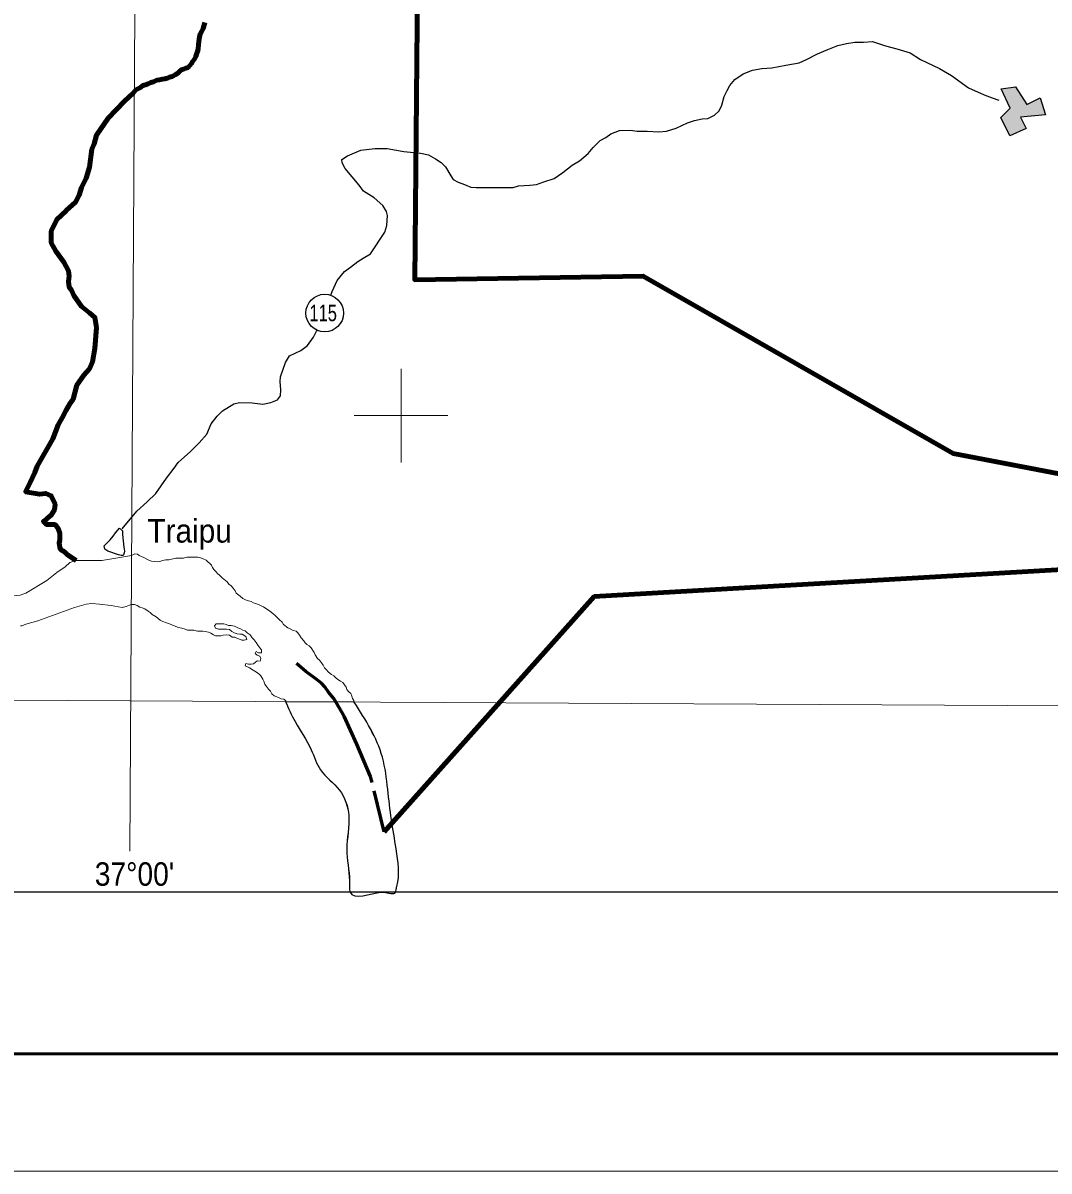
# Model space of a CAD drawing. Extents: x 553962 to 842807, y 8883888 to 9032388.
# Drawn here: x 716936 to 738822, y 8883888 to 8908376 of the extents above; entities that cross this region are included whole.
import ezdxf
from ezdxf.enums import TextEntityAlignment as Align

# ---------------------------------------------------------------- set-up
doc = ezdxf.new("R2010")
doc.units = 0
doc.header["$LTSCALE"] = 150
doc.linetypes.add('LONG_DASH_SHORT_DASH', pattern=[9.9, 6, -1.2, 1.5, -1.2])
for name, color, linetype, lineweight in [('1', 7, 'Continuous', 13), ('12', 7, 'Continuous', 25), ('2', 7, 'Continuous', 13), ('21', 7, 'Continuous', 25), ('24', 7, 'Continuous', 25), ('25', 7, 'Continuous', 13), ('3', 7, 'Continuous', 13), ('48', 7, 'Continuous', 25), ('53', 7, 'Continuous', 106), ('7', 7, 'LONG_DASH_SHORT_DASH', 60), ('9', 7, 'Continuous', 90)]:
    doc.layers.add(name, color=color, linetype=linetype, lineweight=lineweight)
doc.layers.add('41', color=7, linetype='Continuous')
doc.layers.add('46', color=7, linetype='Continuous')

msp = doc.modelspace()

# ---------------------------------------------------------------- hatches: boundary and pattern name
at = {"layer": '21'}
msp.add_hatch(color=256, dxfattribs=at).paths.add_polyline_path([(737801.5, 8906970.9), (738106.6, 8907012.5), (738347.6, 8906633.5), (738630.7, 8906778.2), (738745.6, 8906416), (738212.5, 8906368.9), (738331.1, 8906121.9), (737984.3, 8905966.4), (737794.3, 8906356.6), (737990.6, 8906555.2)])

# ---------------------------------------------------------------- linework, layer by layer
at = {"layer": '1'}
for points in [[(719978.9, 9023574.5), (719561.6, 8949232.2), (719215.6, 8890710.6)], [(564751.7, 8894587.5), (664411.9, 8894209.9), (791388.5, 8893536.2)]]:
    msp.add_lwpolyline(points, dxfattribs=at)
at = {"layer": '12'}
for points in [[(732698.6, 8907406), (732912.6, 8907415.8), (733208.3, 8907476.3), (733493.7, 8907526.8), (733646.8, 8907597.8), (733881.6, 8907714.5), (734106.1, 8907810.9), (734320.4, 8907892), (734498.8, 8907937.5), (734677.2, 8907962.7), (734865.7, 8907967.4), (735054.3, 8907977.3), (735334.1, 8907885.1), (735578.4, 8907823.5), (735863.4, 8907741.4), (736076.8, 8907598.4), (736483.7, 8907404.1), (736742.9, 8907255.9), (737103.6, 8906990.3), (737439.3, 8906842), (737612.3, 8906775.4), (737750.2, 8906727.3)], [(727039.6, 8904864.2), (727284.1, 8904868.9), (727391.1, 8904868.7), (727508.4, 8904899), (727747.9, 8904919), (727890.6, 8904928.9), (728048.7, 8904984.6), (728268, 8905055.5), (728451.9, 8905187.7), (728651.2, 8905340.1), (728809.4, 8905436.6), (728993.4, 8905594.2), (729095.8, 8905716.2), (729249.1, 8905868.8), (729371.7, 8905934.8), (729473.8, 8906011), (729657.5, 8906082), (729896.9, 8906091.7), (730039.5, 8906071.1), (730253.5, 8906065.6), (730497.9, 8906055), (730661, 8906064.9), (730870.1, 8906130.7), (731110, 8906247.4), (731263, 8906293), (731426.1, 8906328.3), (731543.3, 8906338.3), (731686.2, 8906409.4), (731788.5, 8906500.9), (731839.8, 8906623.1), (731891.5, 8906806.3), (731958.2, 8906938.7), (732014.6, 8907040.4), (732122.1, 8907172.7), (732300.8, 8907289.5), (732499.7, 8907365.6), (732698.6, 8907406)], [(723502.8, 8902567), (723531.6, 8902649.7), (723639.5, 8902883.8), (723793, 8903072), (723920.7, 8903168.5), (724079.1, 8903290.5), (724191.4, 8903356.5), (724349.7, 8903453), (724652, 8903916), (724698.3, 8904058.6), (724714.4, 8904272.5), (724689.2, 8904354.1), (724613.3, 8904481.5), (724430.5, 8904644.9), (724201.8, 8904787.9), (724110.5, 8904915.5), (723811.3, 8905272.6), (723745.5, 8905389.9), (723740.7, 8905461.2), (723858.1, 8905542.5), (724143.8, 8905659.1), (724444.6, 8905699.3), (724704.4, 8905698.9), (725060.7, 8905637.1), (725417.2, 8905595.7), (725585.2, 8905564.8), (725732.6, 8905477.9), (725859.7, 8905396.2), (725945.9, 8905304.3), (726062.4, 8905115.6), (726113.1, 8905039.1), (726219.8, 8904977.8), (726352.1, 8904931.7), (726489.4, 8904870.3), (726601.5, 8904865), (727039.6, 8904864.2)], [(719051.7, 8897586.9), (719362.5, 8897965.7), (719587.4, 8898163.9), (719771.5, 8898341.9), (719996.8, 8898667.5), (720160.6, 8898881.1), (720247.7, 8899003.2), (720508.3, 8899237.1), (720697.5, 8899420.1), (720856.1, 8899608.3), (720953.7, 8899827.2), (721076.6, 8899989.9), (721194.2, 8900101.8), (721434.2, 8900254.2), (721551.4, 8900279.4), (721826.5, 8900273.8), (722050.5, 8900248), (722223.9, 8900278.2), (722366.7, 8900339.1), (722428.2, 8900425.6), (722433.7, 8900552.9), (722424.2, 8900726.1), (722429.7, 8900828), (722532.7, 8901133.4), (722624.9, 8901275.9), (722864.7, 8901387.5), (723007.8, 8901494.2), (723130.7, 8901677.4), (723197.4, 8901799.6), (723209.3, 8901823.1)]]:
    msp.add_lwpolyline(points, dxfattribs=at)
at = {"layer": '2'}
for p, q in [((725000, 8899000), (725000, 8901000)), ((724000, 8900000), (726000, 8900000))]:
    msp.add_line(p, q, dxfattribs=at)
at = {"layer": '21'}
for points in [[(737801.5, 8906970.9), (738106.6, 8907012.5), (738347.6, 8906633.5), (738630.7, 8906778.2), (738745.6, 8906416), (738212.5, 8906368.9), (738331.1, 8906121.9), (737984.3, 8905966.4), (737794.3, 8906356.6), (737990.6, 8906555.2)], [(718993.1, 8897599.9), (719057.4, 8897544.6), (719055.9, 8897461.4), (719085.3, 8897192.5), (719103.1, 8897108.8), (719098.1, 8897076.1), (719079.4, 8897033), (719065.5, 8897020), (719028.2, 8897020.1), (718974.7, 8897034.1), (718746.2, 8897111.7), (718679.7, 8897153.1), (718671.6, 8897221.2), (718685, 8897240.1), (718799.2, 8897348.2), (718862.4, 8897430.9), (718906.6, 8897502.9)]]:
    msp.add_lwpolyline(points, close=True, dxfattribs=at)
at = {"layer": '24', "lineweight": 53}
for points in [[(720818, 8908383.6), (720797.2, 8908307.3), (720781.6, 8908256.4), (720750.7, 8908200.6), (720714.6, 8908139.7), (720699, 8908078.7), (720693.5, 8908027.8), (720680.1, 8907917.9)], [(720680.1, 8907917.9), (720671.8, 8907819.1), (720661.2, 8907768.2), (720640.5, 8907712.3), (720624.9, 8907661.5), (720594, 8907605.6), (720558.1, 8907560), (720532.3, 8907509.3), (720496.4, 8907468.7), (720460.5, 8907428.2), (720409.6, 8907413.3), (720363.7, 8907393.2), (720312.7, 8907373.1), (720276.8, 8907337.7), (720241, 8907302.3), (720179.7, 8907267), (720118.4, 8907231.8), (720062.3, 8907216.8), (720016.4, 8907196.8), (719965.5, 8907181.8), (719909.5, 8907177.1), (719843.3, 8907162.2), (719792.3, 8907152.3), (719720.9, 8907122.2), (719664.9, 8907107.3), (719603.6, 8907077.1), (719552.6, 8907057.1), (719496.6, 8907042.2), (719445.4, 8907001.8), (719343.4, 8906951.5), (719283.6, 8906877)], [(719283.6, 8906877), (719100.8, 8906711), (718751.9, 8906345.6), (718502.7, 8905980.3), (718452.8, 8905797.7), (718403, 8905681.4), (718353.1, 8905299.5), (718286.7, 8905067), (718187, 8904867.8), (718137.2, 8904701.7), (718054.1, 8904552.2), (717859.9, 8904374.3), (717854.7, 8904369.6)], [(717854.7, 8904369.6), (717655.3, 8904186.9), (717539, 8903937.8), (717539, 8903688.8), (717638.7, 8903506.1), (717804.9, 8903273.6), (717904.6, 8903091), (717921.2, 8902974.7), (717904.6, 8902858.5), (717921.2, 8902742.3), (717971.1, 8902675.9), (718020.9, 8902559.6), (718187, 8902327.1), (718353.2, 8902194.3), (718469.5, 8902094.7), (718502.7, 8901878.8), (718469.5, 8901430.4), (718419.6, 8901148.2), (718353.2, 8900998.7), (718236.8, 8900865.9), (718087.3, 8900650), (718004.2, 8900351.1), (717937.8, 8900251.5), (717854.7, 8900118.6), (717771.7, 8899952.6), (717688.6, 8899803.1), (717572.3, 8899504.2), (717240, 8898923), (717190.1, 8898790.2), (717090.4, 8898574.3), (716990.8, 8898375.1), (717206.8, 8898341.9), (717289.8, 8898325.2), (717422.7, 8898341.9), (717539, 8898292), (717622.1, 8898109.4), (717605.5, 8897993.1), (717539, 8897876.9), (717472.6, 8897827.1), (717422.7, 8897777.3), (717372.9, 8897744.1), (717439.4, 8897677.6), (717622.1, 8897677.6), (717688.6, 8897594.6), (717721.8, 8897495), (717721.8, 8897395.3), (717721.8, 8897345.5), (717705.2, 8897279.1), (717721.8, 8897196.1), (717738.4, 8897146.3), (717821.5, 8897096.4), (717888, 8897030), (718070.7, 8896913.8)]]:
    msp.add_lwpolyline(points, dxfattribs=at)
at = {"layer": '25', "lineweight": 25}
msp.add_line((724002.8, 8893886.5), (722537.3, 8893896.5), dxfattribs=at)
msp.add_line((724002.8, 8893886.5), (722537.3, 8893896.5), dxfattribs=at)
at = {"layer": '25'}
for points in [[(716671.9, 8896141.4), (716736, 8896160), (716876.8, 8896172.9), (716996.8, 8896216.3), (717443.2, 8896481.3), (717658.9, 8896651.8), (717833.2, 8896772.8), (717934, 8896865.6), (718070.7, 8896913.8), (718220.3, 8896913.8), (718619, 8896913.8), (718918.1, 8896963.6), (719252.2, 8897020.3)], [(719252.2, 8897020.3), (719320.1, 8897049.2), (719376, 8897048.8), (719416.5, 8897018), (719467.2, 8896997.3), (719517.9, 8896971.5), (719578.7, 8896940.5), (719624.3, 8896914.8), (719680.1, 8896894), (719736.1, 8896888.6), (719797.1, 8896883.1), (719858.1, 8896887.8), (719909.1, 8896907.8), (719980.4, 8896922.7), (720046.6, 8896927.3), (720199.4, 8896962), (720255.3, 8896961.7), (720306.2, 8896961.3), (720362.2, 8896961), (720428.4, 8896980.9), (720479.3, 8896980.6), (720540.3, 8896980.2), (720606.4, 8896979.8), (720667.5, 8896979.4), (720723.3, 8896968.8), (720779.1, 8896948.1), (720845, 8896917.1), (720880.4, 8896881.2), (720920.8, 8896845.3), (720956.2, 8896809.4)], [(720956.2, 8896809.4), (720981.3, 8896763.4), (721006.4, 8896717.4), (721046.8, 8896676.4), (721082.2, 8896635.4), (721127.7, 8896594.4), (721188.3, 8896538), (721289.5, 8896455.8), (721329.8, 8896404.6), (721375.3, 8896368.7), (721420.8, 8896322.5), (721461, 8896261.2), (721486.2, 8896215.2), (721567.1, 8896148.4), (721627.8, 8896097.1), (721683.5, 8896071.3), (721749.5, 8896050.5), (721805.3, 8896034.8), (721856, 8896009), (721916.9, 8895988.3), (721972.7, 8895967.5), (722018.4, 8895946.9), (722069, 8895921.1), (722119.7, 8895885.1), (722175.4, 8895854.2), (722231, 8895808), (722271.5, 8895772), (722312, 8895741.2), (722367.5, 8895689.9), (722402.9, 8895654), (722463.5, 8895597.6), (722493.7, 8895546.5), (722584.8, 8895474.6), (722635.5, 8895453.9), (722701.4, 8895417.8), (722762.3, 8895402.1), (722802.7, 8895366.2), (722832.9, 8895320.2), (722873.2, 8895263.9), (722923.6, 8895197.3), (722953.8, 8895151.3), (722994.3, 8895120.5), (723039.9, 8895089.6), (723085.4, 8895048.6), (723145.7, 8894951.4), (723165.7, 8894895.3), (723221.1, 8894818.5), (723261.6, 8894782.6), (723301.9, 8894726.3), (723337.1, 8894675.1), (723367.3, 8894624), (723402.6, 8894583), (723453.1, 8894526.7), (723518.8, 8894475.3), (723564.4, 8894449.5), (723609.9, 8894408.5), (723655.5, 8894372.5), (723706.1, 8894336.6), (723761.8, 8894305.6), (723797.1, 8894259.6), (723827.3, 8894208.4), (723842.2, 8894157.4), (723887.6, 8894111.3), (723928.1, 8894075.3), (723948, 8894019.2)], [(719242.1, 8895974.6), (719137.8, 8895926.7), (719051.9, 8895910.8), (718819, 8895950.7), (718570.6, 8895982.3), (718406.7, 8895992.1), (718284.1, 8895976.8), (718038.4, 8895905.8), (717250.7, 8895623.3), (716998.4, 8895554.6), (716915, 8895518.1), (716881.8, 8895513.8)], [(721516.7, 8895476.3), (721445.7, 8895507.4), (721379.7, 8895523.1), (721323.7, 8895523.4), (721273, 8895544.1), (721222.2, 8895559.7), (721151.1, 8895560.2), (721054.4, 8895560.8), (721023.6, 8895520.3), (721043.6, 8895469.2), (721104.5, 8895443.3), (721160.4, 8895443), (721211.3, 8895442.7), (721277.4, 8895442.2), (721343.5, 8895436.7), (721394.1, 8895395.6), (721444.7, 8895364.7), (721505.6, 8895344), (721561.5, 8895338.5), (721612.4, 8895338.2), (721688.3, 8895286.8), (721708.2, 8895225.5), (721657.3, 8895210.6), (721606.4, 8895210.9), (721555.7, 8895231.6), (721499.9, 8895252.3), (721454.2, 8895273), (721398.3, 8895278.4), (721342.7, 8895319.6), (721276.6, 8895325.1), (721205.3, 8895320.4), (721154.4, 8895305.5), (721098.4, 8895300.7), (721042.5, 8895301.1), (720996.9, 8895326.9), (720941.1, 8895357.8), (720890.4, 8895378.5), (720824.4, 8895399.3), (720773.6, 8895399.6), (720722.7, 8895399.9), (720656.6, 8895405.4), (720580.4, 8895421.2), (720509.3, 8895426.8), (720448.2, 8895427.2), (720397.5, 8895447.9), (720326.5, 8895468.7), (720250.3, 8895484.5), (720158.9, 8895515.6), (720113.3, 8895541.4), (720062.6, 8895557), (719996.6, 8895577.8), (719920.5, 8895608.8), (719864.8, 8895634.7), (719819.3, 8895675.7), (719778.8, 8895711.6), (719692.7, 8895758), (719647.2, 8895799.1), (719606.7, 8895829.9), (719535.8, 8895876.2), (719480.1, 8895902), (719429.3, 8895917.6), (719373.6, 8895948.5), (719317.8, 8895969.3), (719266.9, 8895969.6), (719242.1, 8895974.6)], [(722073.4, 8894336.8), (722053.4, 8894382.8), (722013.2, 8894449.3), (721972.7, 8894485.2), (721917.1, 8894531.4), (721846.2, 8894572.6), (721770.2, 8894618.9), (721724.6, 8894639.6), (721673.9, 8894665.4), (721689.5, 8894716.2), (721745.3, 8894700.6), (721801.3, 8894700.2), (721852.2, 8894705), (721893.1, 8894740.4), (721934, 8894770.7), (721995, 8894765.2), (722010.6, 8894821.2), (721985.5, 8894867.2), (721934.8, 8894893), (721889.3, 8894923.8), (721909.9, 8894969.5), (721960.6, 8894943.7), (722021.6, 8894943.3), (722027.1, 8895004.4), (721986.8, 8895050.5), (721946.5, 8895106.8), (721911.2, 8895163.1), (721871, 8895219.4), (721825.5, 8895260.4), (721780.1, 8895321.8), (721719.4, 8895368.1), (721679, 8895409.1), (721628.2, 8895424.7), (721577.6, 8895455.6), (721516.7, 8895476.3)], [(722537.3, 8893896.5), (722543.5, 8893916.1), (722503.1, 8893952.1), (722447.2, 8893962.6), (722401.6, 8893983.3), (722350.9, 8894004), (722295.1, 8894024.7), (722244.5, 8894065.8), (722214.3, 8894122), (722174, 8894168.1), (722128.6, 8894224.4), (722098.4, 8894270.5), (722073.4, 8894336.8)], [(723948, 8894019.2), (723962.9, 8893968.2), (723993.2, 8893927.2), (724002.8, 8893886.5), (722537.3, 8893896.5)]]:
    msp.add_lwpolyline(points, dxfattribs=at)
at = {"layer": '25', "lineweight": 25}
for points in [[(722537.3, 8893896.5), (722740.6, 8893475.5), (723084.4, 8892873.8), (723285, 8892444), (723686.1, 8892014.3), (723886.7, 8891469.9), (723843.7, 8890753.6), (723901, 8890080.3), (723900.8, 8889934.8), (723915.3, 8889836.7), (724574.3, 8889836.7), (724631.6, 8889836.7), (724883.2, 8889836.5), (724893.2, 8889883.7), (724911.8, 8889958.1), (724898, 8890758.3), (724794.3, 8891380.3), (724717.6, 8892028.6), (724603, 8892716.2), (724002.8, 8893886.5)], [(722537.3, 8893896.5), (722740.6, 8893475.5), (723084.4, 8892873.8), (723285, 8892444), (723686.1, 8892014.3), (723886.7, 8891469.9), (723843.7, 8890753.6), (723901, 8890080.3), (723901.3, 8889998.4)], [(724811.6, 8891262.3), (724794.3, 8891380.3), (724717.6, 8892028.6), (724603, 8892716.2), (724002.8, 8893886.5)]]:
    msp.add_spline(points, degree=3, dxfattribs=at)
at = {"layer": '3'}
msp.add_lwpolyline([(842807.3, 9032387.8), (842807.3, 8883887.8), (553961.7, 8883887.8), (553961.7, 9032387.8)], close=True, dxfattribs=at)
at = {"layer": '3', "lineweight": 53}
msp.add_lwpolyline([(840307.3, 9029887.8), (840307.3, 8886387.8), (560211.7, 8886387.8), (560211.7, 9029887.8)], close=True, dxfattribs=at)
at = {"layer": '3', "lineweight": 25}
msp.add_lwpolyline([(563033.9, 9026438.8), (793061.1, 9026438.8), (793495.6, 8889836.8), (563468.3, 8889836.8)], close=True, dxfattribs=at)
at = {"layer": '48'}
msp.add_circle((723371.8, 8902188.1), 401.3, dxfattribs=at)
at = {"layer": '53'}
for points in [[(720818, 8908383.6), (720797.2, 8908307.3), (720781.6, 8908256.4), (720750.7, 8908200.6), (720714.6, 8908139.7), (720699, 8908078.7), (720693.5, 8908027.8), (720680.1, 8907917.9)], [(720818, 8908383.6), (720797.2, 8908307.3), (720781.6, 8908256.4), (720750.7, 8908200.6), (720714.6, 8908139.7), (720699, 8908078.7), (720693.5, 8908027.8), (720680.1, 8907917.9)], [(720818, 8908383.6), (720797.2, 8908307.3), (720781.6, 8908256.4), (720750.7, 8908200.6), (720714.6, 8908139.7), (720699, 8908078.7), (720693.5, 8908027.8), (720680.1, 8907917.9)], [(720680.1, 8907917.9), (720671.8, 8907819.1), (720661.2, 8907768.2), (720640.5, 8907712.3), (720624.9, 8907661.5), (720594, 8907605.6), (720558.1, 8907560), (720532.3, 8907509.3), (720496.4, 8907468.7), (720460.5, 8907428.2), (720409.6, 8907413.3), (720363.7, 8907393.2), (720312.7, 8907373.1), (720276.8, 8907337.7), (720241, 8907302.3), (720179.7, 8907267), (720118.4, 8907231.8), (720062.3, 8907216.8), (720016.4, 8907196.8), (719965.5, 8907181.8), (719909.5, 8907177.1), (719843.3, 8907162.2), (719792.3, 8907152.3), (719720.9, 8907122.2), (719664.9, 8907107.3), (719603.6, 8907077.1), (719552.6, 8907057.1), (719496.6, 8907042.2), (719445.4, 8907001.8), (719343.4, 8906951.5), (719283.6, 8906877)], [(720680.1, 8907917.9), (720671.8, 8907819.1), (720661.2, 8907768.2), (720640.5, 8907712.3), (720624.9, 8907661.5), (720594, 8907605.6), (720558.1, 8907560), (720532.3, 8907509.3), (720496.4, 8907468.7), (720460.5, 8907428.2), (720409.6, 8907413.3), (720363.7, 8907393.2), (720312.7, 8907373.1), (720276.8, 8907337.7), (720241, 8907302.3), (720179.7, 8907267), (720118.4, 8907231.8), (720062.3, 8907216.8), (720016.4, 8907196.8), (719965.5, 8907181.8), (719909.5, 8907177.1), (719843.3, 8907162.2), (719792.3, 8907152.3), (719720.9, 8907122.2), (719664.9, 8907107.3), (719603.6, 8907077.1), (719552.6, 8907057.1), (719496.6, 8907042.2), (719445.4, 8907001.8), (719343.4, 8906951.5), (719283.6, 8906877)], [(720680.1, 8907917.9), (720671.8, 8907819.1), (720661.2, 8907768.2), (720640.5, 8907712.3), (720624.9, 8907661.5), (720594, 8907605.6), (720558.1, 8907560), (720532.3, 8907509.3), (720496.4, 8907468.7), (720460.5, 8907428.2), (720409.6, 8907413.3), (720363.7, 8907393.2), (720312.7, 8907373.1), (720276.8, 8907337.7), (720241, 8907302.3), (720179.7, 8907267), (720118.4, 8907231.8), (720062.3, 8907216.8), (720016.4, 8907196.8), (719965.5, 8907181.8), (719909.5, 8907177.1), (719843.3, 8907162.2), (719792.3, 8907152.3), (719720.9, 8907122.2), (719664.9, 8907107.3), (719603.6, 8907077.1), (719552.6, 8907057.1), (719496.6, 8907042.2), (719445.4, 8907001.8), (719343.4, 8906951.5), (719283.6, 8906877)], [(719283.6, 8906877), (719100.8, 8906711), (718751.9, 8906345.6), (718502.7, 8905980.3), (718452.8, 8905797.7), (718403, 8905681.4), (718353.1, 8905299.5), (718286.7, 8905067), (718187, 8904867.8), (718137.2, 8904701.7), (718054.1, 8904552.2), (717859.9, 8904374.3), (717854.7, 8904369.6)], [(719283.6, 8906877), (719100.8, 8906711), (718751.9, 8906345.6), (718502.7, 8905980.3), (718452.8, 8905797.7), (718403, 8905681.4), (718353.1, 8905299.5), (718286.7, 8905067), (718187, 8904867.8), (718137.2, 8904701.7), (718054.1, 8904552.2), (717859.9, 8904374.3), (717854.7, 8904369.6)], [(719283.6, 8906877), (719100.8, 8906711), (718751.9, 8906345.6), (718502.7, 8905980.3), (718452.8, 8905797.7), (718403, 8905681.4), (718353.1, 8905299.5), (718286.7, 8905067), (718187, 8904867.8), (718137.2, 8904701.7), (718054.1, 8904552.2), (717859.9, 8904374.3), (717854.7, 8904369.6)], [(717854.7, 8904369.6), (717655.3, 8904186.9), (717539, 8903937.8), (717539, 8903688.8), (717638.7, 8903506.1), (717804.9, 8903273.6), (717904.6, 8903091), (717921.2, 8902974.7), (717904.6, 8902858.5), (717921.2, 8902742.3), (717971.1, 8902675.9), (718020.9, 8902559.6), (718187, 8902327.1), (718353.2, 8902194.3), (718469.5, 8902094.7), (718502.7, 8901878.8), (718469.5, 8901430.4), (718419.6, 8901148.2), (718353.2, 8900998.7), (718236.8, 8900865.9), (718087.3, 8900650), (718004.2, 8900351.1), (717937.8, 8900251.5), (717854.7, 8900118.6), (717771.7, 8899952.6), (717688.6, 8899803.1), (717572.3, 8899504.2), (717240, 8898923), (717190.1, 8898790.2), (717090.4, 8898574.3), (716990.8, 8898375.1), (717206.8, 8898341.9), (717289.8, 8898325.2), (717422.7, 8898341.9), (717539, 8898292), (717622.1, 8898109.4), (717605.5, 8897993.1), (717539, 8897876.9), (717472.6, 8897827.1), (717422.7, 8897777.3), (717372.9, 8897744.1), (717439.4, 8897677.6), (717622.1, 8897677.6), (717688.6, 8897594.6), (717721.8, 8897495), (717721.8, 8897395.3), (717721.8, 8897345.5), (717705.2, 8897279.1), (717721.8, 8897196.1), (717738.4, 8897146.3), (717821.5, 8897096.4), (717888, 8897030), (718070.7, 8896913.8)], [(717854.7, 8904369.6), (717655.3, 8904186.9), (717539, 8903937.8), (717539, 8903688.8), (717638.7, 8903506.1), (717804.9, 8903273.6), (717904.6, 8903091), (717921.2, 8902974.7), (717904.6, 8902858.5), (717921.2, 8902742.3), (717971.1, 8902675.9), (718020.9, 8902559.6), (718187, 8902327.1), (718353.2, 8902194.3), (718469.5, 8902094.7), (718502.7, 8901878.8), (718469.5, 8901430.4), (718419.6, 8901148.2), (718353.2, 8900998.7), (718236.8, 8900865.9), (718087.3, 8900650), (718004.2, 8900351.1), (717937.8, 8900251.5), (717854.7, 8900118.6), (717771.7, 8899952.6), (717688.6, 8899803.1), (717572.3, 8899504.2), (717240, 8898923), (717190.1, 8898790.2), (717090.4, 8898574.3), (716990.8, 8898375.1), (717206.8, 8898341.9), (717289.8, 8898325.2), (717422.7, 8898341.9), (717539, 8898292), (717622.1, 8898109.4), (717605.5, 8897993.1), (717539, 8897876.9), (717472.6, 8897827.1), (717422.7, 8897777.3), (717372.9, 8897744.1), (717439.4, 8897677.6), (717622.1, 8897677.6), (717688.6, 8897594.6), (717721.8, 8897495), (717721.8, 8897395.3), (717721.8, 8897345.5), (717705.2, 8897279.1), (717721.8, 8897196.1), (717738.4, 8897146.3), (717821.5, 8897096.4), (717888, 8897030), (718070.7, 8896913.8)], [(717854.7, 8904369.6), (717655.3, 8904186.9), (717539, 8903937.8), (717539, 8903688.8), (717638.7, 8903506.1), (717804.9, 8903273.6), (717904.6, 8903091), (717921.2, 8902974.7), (717904.6, 8902858.5), (717921.2, 8902742.3), (717971.1, 8902675.9), (718020.9, 8902559.6), (718187, 8902327.1), (718353.2, 8902194.3), (718469.5, 8902094.7), (718502.7, 8901878.8), (718469.5, 8901430.4), (718419.6, 8901148.2), (718353.2, 8900998.7), (718236.8, 8900865.9), (718087.3, 8900650), (718004.2, 8900351.1), (717937.8, 8900251.5), (717854.7, 8900118.6), (717771.7, 8899952.6), (717688.6, 8899803.1), (717572.3, 8899504.2), (717240, 8898923), (717190.1, 8898790.2), (717090.4, 8898574.3), (716990.8, 8898375.1), (717206.8, 8898341.9), (717289.8, 8898325.2), (717422.7, 8898341.9), (717539, 8898292), (717622.1, 8898109.4), (717605.5, 8897993.1), (717539, 8897876.9), (717472.6, 8897827.1), (717422.7, 8897777.3), (717372.9, 8897744.1), (717439.4, 8897677.6), (717622.1, 8897677.6), (717688.6, 8897594.6), (717721.8, 8897495), (717721.8, 8897395.3), (717721.8, 8897345.5), (717705.2, 8897279.1), (717721.8, 8897196.1), (717738.4, 8897146.3), (717821.5, 8897096.4), (717888, 8897030), (718070.7, 8896913.8)]]:
    msp.add_lwpolyline(points, dxfattribs=at)
at = {"layer": '7'}
msp.add_lwpolyline([(724638.9, 8891123.6), (724349.6, 8892305.9), (724059.6, 8892992.2), (723788.9, 8893591.5), (723566.6, 8893968.5), (723450.6, 8894103.8), (723373.3, 8894219.2), (723307.3, 8894290.7), (723154.9, 8894408.1), (722972, 8894546), (722773.8, 8894710.7)], dxfattribs=at)
at = {"layer": '9'}
msp.add_line((741371.9, 8898310.2), (736775.3, 8899194.4), dxfattribs=at)
for points in [[(741371.9, 8898310.2), (736775.3, 8899194.4), (730163.4, 8902976.8), (725291.2, 8902898), (725401.2, 8914588.3), (719613.1, 8922670.1)], [(724638.9, 8891123.6), (729122.2, 8896139.1), (740717.5, 8896813.6), (741371.9, 8898310.2)]]:
    msp.add_lwpolyline(points, dxfattribs=at)

# ---------------------------------------------------------------- texts
at = {"layer": '41', "width": 0.95}
msp.add_text('Traipu', height=500, dxfattribs=at).set_placement((719591.1, 8897292.6))
at = {"layer": '46', "width": 0.9}
msp.add_text("37°00'", height=500, dxfattribs=at).set_placement((719315, 8889973.1), align=Align.CENTER)
at = {"layer": '48', "width": 0.75}
msp.add_text('115', height=350, dxfattribs=at).set_placement((723340.2, 8902014.7), align=Align.CENTER)

doc.saveas('drawing.dxf')
